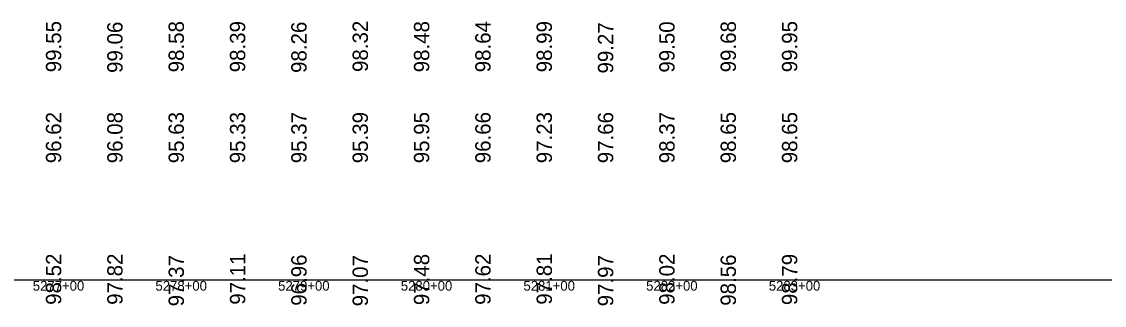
# Model space of a CAD drawing. Extents: x 2147288 to 2220488, y 740833 to 759333.
# Drawn here: x 2210048 to 2210930, y 750062 to 750294 of the extents above; entities that cross this region are included whole.
import ezdxf

# ---------------------------------------------------------------- set-up
doc = ezdxf.new("R2010")
doc.units = 0
for name, color, linetype in [('RD_DDB_Profile_EX', 7, 'Continuous'), ('RD_DDB_StaTX', 7, 'Continuous'), ('RD_DDB_StripGrade', 7, 'Continuous'), ('RD_GPK_Profile_Cell', 7, 'Continuous')]:
    doc.layers.add(name, color=color, linetype=linetype)

msp = doc.modelspace()

# ---------------------------------------------------------------- linework, layer by layer
at = {"layer": 'RD_GPK_Profile_Cell'}
msp.add_line((2198888.28, 750083.43), (2220488.28, 750083.43), dxfattribs=at)

# ---------------------------------------------------------------- texts
at = {"layer": 'RD_DDB_Profile_EX'}
for s, p in [('99.55', (2210080.08, 750252.69)), ('99.06', (2210130.08, 750252.13)), ('98.58', (2210180.08, 750252.64)), ('98.39', (2210230.08, 750252.64)), ('98.26', (2210280.08, 750252.13)), ('98.32', (2210330.08, 750252.89)), ('98.48', (2210380.08, 750252.64)), ('98.64', (2210430.08, 750252.66)), ('98.99', (2210480.08, 750252.64)), ('99.27', (2210530.08, 750251.67)), ('99.50', (2210580.08, 750252.38)), ('99.68', (2210630.08, 750252.64)), ('99.95', (2210680.08, 750252.69)), ('98.52', (2210080.08, 750062.89)), ('97.82', (2210130.08, 750062.89)), ('97.37', (2210180.08, 750061.67)), ('97.11', (2210230.08, 750063)), ('96.96', (2210280.08, 750062.13)), ('97.07', (2210330.08, 750061.67)), ('97.48', (2210380.08, 750062.64)), ('97.62', (2210430.08, 750062.89)), ('97.81', (2210480.08, 750063)), ('97.97', (2210530.08, 750061.67)), ('98.02', (2210580.08, 750062.89)), ('98.56', (2210630.08, 750062.13)), ('98.79', (2210680.08, 750062.64))]:
    msp.add_text(s, height=12.5, rotation=90, dxfattribs=at).set_placement(p)
at = {"layer": 'RD_DDB_StaTX'}
for s, p in [('5277+00', (2210056.88, 750074.43)), ('5277+00', (2210056.88, 750074.43)), ('5277+00', (2210056.88, 750074.43)), ('5278+00', (2210156.88, 750074.43)), ('5278+00', (2210156.88, 750074.43)), ('5278+00', (2210156.88, 750074.43)), ('5279+00', (2210256.88, 750074.43)), ('5279+00', (2210256.88, 750074.43)), ('5279+00', (2210256.88, 750074.43)), ('5280+00', (2210356.88, 750074.43)), ('5280+00', (2210356.88, 750074.43)), ('5280+00', (2210356.88, 750074.43)), ('5281+00', (2210456.88, 750074.43)), ('5281+00', (2210456.88, 750074.43)), ('5281+00', (2210456.88, 750074.43)), ('5282+00', (2210556.88, 750074.43)), ('5282+00', (2210556.88, 750074.43)), ('5282+00', (2210556.88, 750074.43)), ('5283+00', (2210656.88, 750074.43)), ('5283+00', (2210656.88, 750074.43)), ('5283+00', (2210656.88, 750074.43))]:
    msp.add_text(s, height=8, dxfattribs=at).set_placement(p)
at = {"layer": 'RD_DDB_StripGrade'}
for s, p in [('96.62', (2210080.08, 750178.43)), ('96.08', (2210130.08, 750178.43)), ('95.63', (2210180.08, 750178.43)), ('95.33', (2210230.08, 750178.43)), ('95.37', (2210280.08, 750178.43)), ('95.39', (2210330.08, 750178.43)), ('95.95', (2210380.08, 750178.43)), ('96.66', (2210430.08, 750178.43)), ('97.23', (2210480.08, 750178.43)), ('97.66', (2210530.08, 750178.43)), ('98.37', (2210580.08, 750178.43)), ('98.65', (2210630.08, 750178.43)), ('98.65', (2210680.08, 750178.43))]:
    msp.add_text(s, height=12.5, rotation=90, dxfattribs=at).set_placement(p)

doc.saveas('drawing.dxf')
